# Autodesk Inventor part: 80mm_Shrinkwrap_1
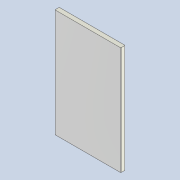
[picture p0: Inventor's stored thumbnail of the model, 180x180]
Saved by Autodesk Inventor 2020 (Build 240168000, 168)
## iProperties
Created: 2020-11
Part Number: 80mm_Shrinkwrap_1
Material: Generic
Document SubType Name: Modeling
Designer: Yolande
Density: 1 g/cm^3
Appearance: Default
Author: Yolande
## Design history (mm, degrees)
derived "80mm.iam"
body "Solid1"
node "Lambdaboard 80mm Mineral White.ipt:1" dims "d0" = 10
